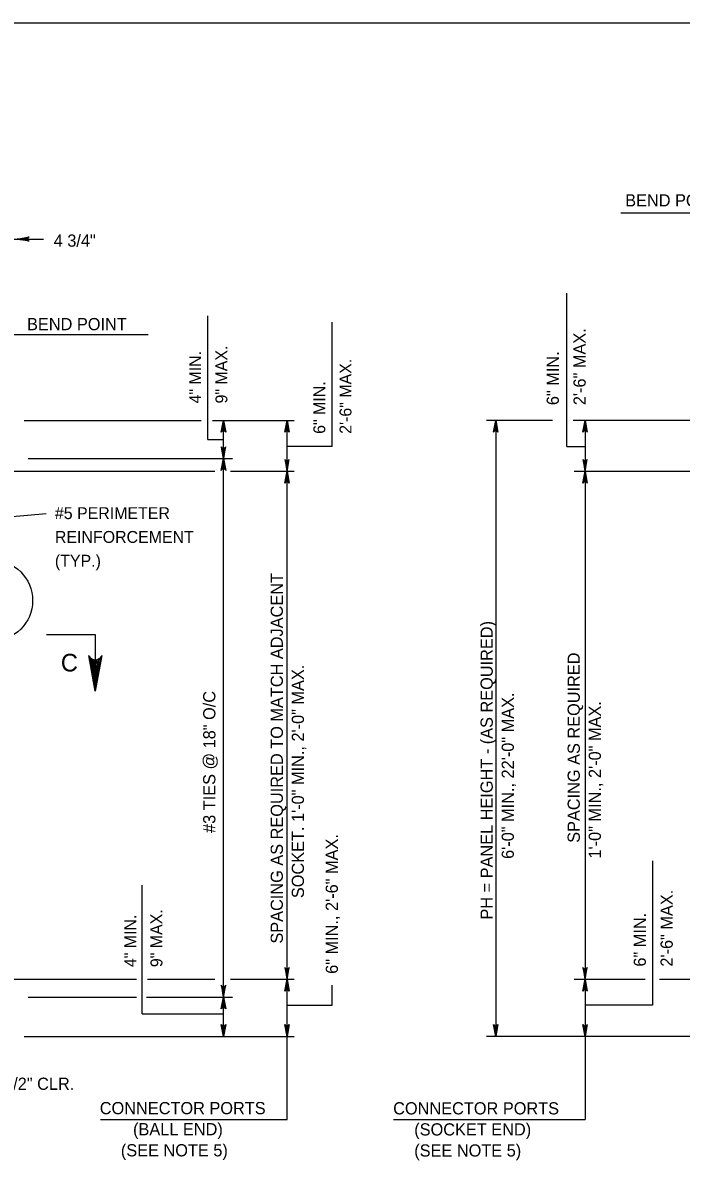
# Model space of a CAD drawing. Extents: x 3385 to 6532, y -616 to 1166.
# Drawn here: x 5710 to 5875.8, y 270.1 to 556.7 of the extents above; entities that cross this region are included whole.
import ezdxf

# ---------------------------------------------------------------- set-up
doc = ezdxf.new("R2010")
doc.units = 0
doc.layers.add('1', color=7, linetype='Continuous')
doc.layers.add('2', color=7, linetype='Continuous')

msp = doc.modelspace()

# ---------------------------------------------------------------- linework, layer by layer
at = {"layer": '1'}
for p, q in [((5860.61, 508.82), (5895.27, 508.82)), ((5547.47, 502.2), (5715.29, 502.2)), ((5847.02, 449.97), (5847.02, 488.58)), ((5756.62, 451.74), (5756.62, 482.89)), ((5787.96, 449.97), (5787.96, 481.26)), ((5703.6, 478.15), (5741.6, 478.15)), ((5710.36, 456.51), (5754.96, 456.51)), ((5757.81, 456.51), (5778.38, 456.51)), ((5760.59, 301.32), (5760.59, 456.51)), ((5776.59, 280.42), (5776.59, 456.51)), ((5843.44, 456.51), (5826.79, 456.51)), ((5829.12, 456.51), (5829.12, 301.32)), ((5896.39, 456.51), (5848.64, 456.51)), ((5851.64, 456.51), (5851.64, 280.42)), ((5756.62, 451.74), (5760.59, 451.74)), ((5787.96, 449.97), (5776.59, 449.97)), ((5847.02, 449.97), (5851.64, 449.97)), ((5711.41, 446.91), (5762.89, 446.91)), ((5705.02, 443.71), (5758.38, 443.71)), ((5762.36, 443.71), (5778.38, 443.71)), ((5848.87, 443.71), (5896.39, 443.71)), ((5715.96, 432.96), (5703.6, 431.85)), ((5716.05, 402.62), (5728.31, 402.62)), ((5728.31, 402.62), (5728.31, 388.35)), ((5868.65, 345.57), (5868.65, 309.18)), ((5740.1, 307.01), (5740.1, 339.47)), ((5707.27, 315.72), (5738.64, 315.72)), ((5741.43, 315.72), (5758.38, 315.72)), ((5762.36, 315.72), (5778.38, 315.72)), ((5848.87, 315.72), (5866.77, 315.72)), ((5870.36, 315.72), (5896.39, 315.72)), ((5787.96, 309.18), (5787.96, 314.29)), ((5711.41, 311.26), (5738.64, 311.26)), ((5741.19, 311.26), (5762.89, 311.26)), ((5740.1, 307.01), (5760.59, 307.01)), ((5776.59, 309.18), (5787.96, 309.18)), ((5868.65, 309.18), (5851.64, 309.18)), ((5710.36, 301.32), (5778.38, 301.32)), ((5896.39, 301.32), (5826.79, 301.32)), ((5729.65, 280.42), (5776.59, 280.42)), ((5803.38, 280.42), (5851.64, 280.42))]:
    msp.add_line(p, q, dxfattribs=at)
for points in [[(5708.66, 502.2), (5711.64, 502.76), (5711.41, 502.6), (5711.29, 502.4), (5711.26, 502.2), (5711.29, 502), (5711.41, 501.8), (5711.64, 501.64), (5708.66, 502.2), (5711.41, 501.8), (5711.29, 502), (5708.66, 502.2), (5711.26, 502.2), (5711.29, 502.4), (5708.66, 502.2), (5711.41, 502.6)], [(5760.59, 456.51), (5761.15, 453.53), (5761.07, 453.65), (5760.99, 453.76), (5760.89, 453.82), (5760.79, 453.88), (5760.69, 453.9), (5760.59, 453.91), (5760.49, 453.9), (5760.39, 453.88), (5760.29, 453.82), (5760.19, 453.76), (5760.11, 453.65), (5760.03, 453.53), (5760.59, 456.51), (5760.11, 453.65), (5760.19, 453.76), (5760.59, 456.51), (5760.29, 453.82), (5760.39, 453.88), (5760.59, 456.51), (5760.49, 453.9), (5760.59, 453.91), (5760.59, 456.51), (5760.69, 453.9), (5760.79, 453.88), (5760.59, 456.51), (5760.89, 453.82), (5760.99, 453.76), (5760.59, 456.51), (5761.07, 453.65)], [(5776.59, 456.51), (5777.15, 453.53), (5776.99, 453.76), (5776.79, 453.88), (5776.59, 453.91), (5776.39, 453.88), (5776.19, 453.76), (5776.03, 453.53), (5776.59, 456.51), (5776.19, 453.76), (5776.39, 453.88), (5776.59, 456.51), (5776.59, 453.91), (5776.79, 453.88), (5776.59, 456.51), (5776.99, 453.76)], [(5829.12, 456.51), (5829.68, 453.53), (5829.52, 453.76), (5829.32, 453.88), (5829.12, 453.91), (5828.92, 453.88), (5828.72, 453.76), (5828.56, 453.53), (5829.12, 456.51), (5828.72, 453.76), (5828.92, 453.88), (5829.12, 456.51), (5829.12, 453.91), (5829.32, 453.88), (5829.12, 456.51), (5829.52, 453.76)], [(5851.64, 456.51), (5852.2, 453.53), (5852.04, 453.76), (5851.84, 453.88), (5851.64, 453.91), (5851.44, 453.88), (5851.24, 453.76), (5851.09, 453.53), (5851.64, 456.51), (5851.24, 453.76), (5851.44, 453.88), (5851.64, 456.51), (5851.64, 453.91), (5851.84, 453.88), (5851.64, 456.51), (5852.04, 453.76)], [(5760.59, 446.91), (5761.15, 449.9), (5761.07, 449.78), (5760.99, 449.67), (5760.89, 449.61), (5760.79, 449.55), (5760.69, 449.53), (5760.59, 449.51), (5760.49, 449.53), (5760.39, 449.55), (5760.29, 449.61), (5760.19, 449.67), (5760.11, 449.78), (5760.03, 449.9), (5760.59, 446.91), (5760.11, 449.78), (5760.19, 449.67), (5760.59, 446.91), (5760.29, 449.61), (5760.39, 449.55), (5760.59, 446.91), (5760.49, 449.53), (5760.59, 449.51), (5760.59, 446.91), (5760.69, 449.53), (5760.79, 449.55), (5760.59, 446.91), (5760.89, 449.61), (5760.99, 449.67), (5760.59, 446.91), (5761.07, 449.78)], [(5760.59, 446.91), (5761.15, 443.93), (5761.07, 444.05), (5760.99, 444.16), (5760.89, 444.22), (5760.79, 444.28), (5760.69, 444.3), (5760.59, 444.31), (5760.49, 444.3), (5760.39, 444.28), (5760.29, 444.22), (5760.19, 444.16), (5760.11, 444.05), (5760.03, 443.93), (5760.59, 446.91), (5760.11, 444.05), (5760.19, 444.16), (5760.59, 446.91), (5760.29, 444.22), (5760.39, 444.28), (5760.59, 446.91), (5760.49, 444.3), (5760.59, 444.31), (5760.59, 446.91), (5760.69, 444.3), (5760.79, 444.28), (5760.59, 446.91), (5760.89, 444.22), (5760.99, 444.16), (5760.59, 446.91), (5761.07, 444.05)], [(5776.59, 443.71), (5777.15, 446.7), (5776.99, 446.47), (5776.79, 446.35), (5776.59, 446.31), (5776.39, 446.35), (5776.19, 446.47), (5776.03, 446.7), (5776.59, 443.71), (5776.19, 446.47), (5776.39, 446.35), (5776.59, 443.71), (5776.59, 446.31), (5776.79, 446.35), (5776.59, 443.71), (5776.99, 446.47)], [(5851.64, 443.71), (5852.2, 446.7), (5852.04, 446.47), (5851.84, 446.35), (5851.64, 446.31), (5851.44, 446.35), (5851.24, 446.47), (5851.09, 446.7), (5851.64, 443.71), (5851.24, 446.47), (5851.44, 446.35), (5851.64, 443.71), (5851.64, 446.31), (5851.84, 446.35), (5851.64, 443.71), (5852.04, 446.47)], [(5776.59, 443.71), (5777.15, 440.73), (5776.99, 440.96), (5776.79, 441.08), (5776.59, 441.11), (5776.39, 441.08), (5776.19, 440.96), (5776.03, 440.73), (5776.59, 443.71), (5776.19, 440.96), (5776.39, 441.08), (5776.59, 443.71), (5776.59, 441.11), (5776.79, 441.08), (5776.59, 443.71), (5776.99, 440.96)], [(5851.64, 443.71), (5852.2, 440.73), (5852.04, 440.96), (5851.84, 441.08), (5851.64, 441.11), (5851.44, 441.08), (5851.24, 440.96), (5851.09, 440.73), (5851.64, 443.71), (5851.24, 440.96), (5851.44, 441.08), (5851.64, 443.71), (5851.64, 441.11), (5851.84, 441.08), (5851.64, 443.71), (5852.04, 440.96)], [(5728.31, 388.35), (5726.64, 397.3), (5726.88, 396.95), (5727.11, 396.61), (5727.41, 396.43), (5727.71, 396.25), (5728.01, 396.2), (5728.31, 396.15), (5728.61, 396.2), (5728.91, 396.25), (5729.21, 396.43), (5729.51, 396.61), (5729.75, 396.95), (5729.99, 397.3), (5728.31, 388.35), (5729.75, 396.95), (5729.51, 396.61), (5728.31, 388.35), (5729.21, 396.43), (5728.91, 396.25), (5728.31, 388.35), (5728.61, 396.2), (5728.31, 396.15), (5728.31, 388.35), (5728.01, 396.2), (5727.71, 396.25), (5728.31, 388.35), (5727.41, 396.43), (5727.11, 396.61), (5728.31, 388.35), (5726.88, 396.95)], [(5776.59, 315.72), (5777.15, 318.7), (5776.99, 318.47), (5776.79, 318.35), (5776.59, 318.32), (5776.39, 318.35), (5776.19, 318.47), (5776.03, 318.7), (5776.59, 315.72), (5776.19, 318.47), (5776.39, 318.35), (5776.59, 315.72), (5776.59, 318.32), (5776.79, 318.35), (5776.59, 315.72), (5776.99, 318.47)], [(5851.64, 315.72), (5852.2, 318.7), (5852.04, 318.47), (5851.84, 318.35), (5851.64, 318.32), (5851.44, 318.35), (5851.24, 318.47), (5851.09, 318.7), (5851.64, 315.72), (5851.24, 318.47), (5851.44, 318.35), (5851.64, 315.72), (5851.64, 318.32), (5851.84, 318.35), (5851.64, 315.72), (5852.04, 318.47)], [(5776.59, 315.72), (5777.15, 312.73), (5776.99, 312.96), (5776.79, 313.08), (5776.59, 313.12), (5776.39, 313.08), (5776.19, 312.96), (5776.03, 312.73), (5776.59, 315.72), (5776.19, 312.96), (5776.39, 313.08), (5776.59, 315.72), (5776.59, 313.12), (5776.79, 313.08), (5776.59, 315.72), (5776.99, 312.96)], [(5851.64, 315.72), (5852.2, 312.73), (5852.04, 312.96), (5851.84, 313.08), (5851.64, 313.12), (5851.44, 313.08), (5851.24, 312.96), (5851.09, 312.73), (5851.64, 315.72), (5851.24, 312.96), (5851.44, 313.08), (5851.64, 315.72), (5851.64, 313.12), (5851.84, 313.08), (5851.64, 315.72), (5852.04, 312.96)], [(5760.59, 311.26), (5761.15, 314.24), (5760.99, 314.01), (5760.79, 313.89), (5760.59, 313.86), (5760.39, 313.89), (5760.19, 314.01), (5760.03, 314.24), (5760.59, 311.26), (5760.19, 314.01), (5760.39, 313.89), (5760.59, 311.26), (5760.59, 313.86), (5760.79, 313.89), (5760.59, 311.26), (5760.99, 314.01)], [(5760.59, 311.26), (5761.15, 308.27), (5760.99, 308.5), (5760.79, 308.62), (5760.59, 308.66), (5760.39, 308.62), (5760.19, 308.5), (5760.03, 308.27), (5760.59, 311.26), (5760.19, 308.5), (5760.39, 308.62), (5760.59, 311.26), (5760.59, 308.66), (5760.79, 308.62), (5760.59, 311.26), (5760.99, 308.5)], [(5760.59, 301.32), (5760.03, 304.3), (5760.19, 304.07), (5760.39, 303.95), (5760.59, 303.92), (5760.79, 303.95), (5760.99, 304.07), (5761.15, 304.3), (5760.59, 301.32), (5760.99, 304.07), (5760.79, 303.95), (5760.59, 301.32), (5760.59, 303.92), (5760.39, 303.95), (5760.59, 301.32), (5760.19, 304.07)], [(5776.59, 301.32), (5776.03, 304.3), (5776.19, 304.07), (5776.39, 303.95), (5776.59, 303.92), (5776.79, 303.95), (5776.99, 304.07), (5777.15, 304.3), (5776.59, 301.32), (5776.99, 304.07), (5776.79, 303.95), (5776.59, 301.32), (5776.59, 303.92), (5776.39, 303.95), (5776.59, 301.32), (5776.19, 304.07)], [(5829.12, 301.32), (5828.56, 304.3), (5828.72, 304.07), (5828.92, 303.95), (5829.12, 303.92), (5829.32, 303.95), (5829.52, 304.07), (5829.68, 304.3), (5829.12, 301.32), (5829.52, 304.07), (5829.32, 303.95), (5829.12, 301.32), (5829.12, 303.92), (5828.92, 303.95), (5829.12, 301.32), (5828.72, 304.07)], [(5851.64, 301.32), (5851.09, 304.3), (5851.24, 304.07), (5851.44, 303.95), (5851.64, 303.92), (5851.84, 303.95), (5852.04, 304.07), (5852.2, 304.3), (5851.64, 301.32), (5852.04, 304.07), (5851.84, 303.95), (5851.64, 301.32), (5851.64, 303.92), (5851.44, 303.95), (5851.64, 301.32), (5851.24, 304.07)]]:
    msp.add_lwpolyline(points, dxfattribs=at)
msp.add_circle((5702.27, 411.14), 10.24, dxfattribs=at)
at = {"layer": '2'}
msp.add_line((5483.34, 556.69), (6269.34, 556.69), dxfattribs=at)

# ---------------------------------------------------------------- texts
at = {"layer": '1'}
for s, height, p in [('BEND POINT', 3.072, (5861.74, 510.42)), ('4 3/4"', 3.072, (5717.83, 500.28)), ('BEND POINT', 3.072, (5711.12, 479.24)), ('#5 PERIMETER', 3, (5718.13, 431.66)), ('REINFORCEMENT', 3, (5718.13, 425.66)), ('(TYP.)', 3, (5718.13, 419.66)), ('C', 4.45, (5719.63, 393.27)), ('1 1/2" CLR.', 3.072, (5701.92, 287.88)), ('CONNECTOR PORTS', 3.072, (5729.43, 281.74)), ('CONNECTOR PORTS', 3.072, (5803.31, 281.69)), ('(BALL END)', 3.072, (5737.81, 276.43)), ('(SOCKET END)', 3.072, (5808.62, 276.38)), ('(SEE NOTE 5)', 3.072, (5734.74, 271.12)), ('(SEE NOTE 5)', 3.072, (5808.62, 271.07))]:
    msp.add_text(s, height=height, dxfattribs=at).set_placement(p)
for s, height, p in [('2\'-6" MAX.', 3.072, (5851.79, 460.36)), ('4" MIN.', 3, (5754.96, 460.79)), ('9" MAX.', 3, (5761.56, 460.79)), ('6" MIN.', 3.072, (5845.03, 460.36)), ('2\'-6" MAX.', 3, (5792.81, 453.13)), ('6" MIN.', 3, (5786.21, 453.13)), ('SPACING AS REQUIRED TO MATCH ADJACENT', 3.072, (5775.54, 324.72)), ('PH = PANEL HEIGHT - (AS REQUIRED)', 3.072, (5828.39, 330.77)), ('SPACING AS REQUIRED', 3.072, (5850.31, 350.11)), ('SOCKET. 1\'-0" MIN., 2\'-0" MAX.', 3.072, (5780.85, 336.17)), ('#3 TIES @ 18" O/C', 3.072, (5758.54, 352.6)), ('6\'-0" MIN., 22\'-0" MAX.', 3.072, (5833.7, 346.05)), ('1\'-0" MIN., 2\'-0" MAX.', 3.072, (5855.62, 346.15)), ('6" MIN., 2\'-6" MAX.', 3.072, (5789.39, 317.1)), ('2\'-6" MAX.', 3.072, (5873.71, 318.92)), ('9" MAX.', 3, (5745.2, 318.79)), ('4" MIN.', 3, (5738.6, 318.79)), ('6" MIN.', 3.072, (5866.95, 318.92))]:
    msp.add_text(s, height=height, rotation=90, dxfattribs=at).set_placement(p)

doc.saveas('drawing.dxf')
